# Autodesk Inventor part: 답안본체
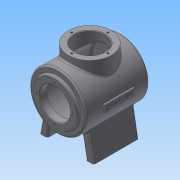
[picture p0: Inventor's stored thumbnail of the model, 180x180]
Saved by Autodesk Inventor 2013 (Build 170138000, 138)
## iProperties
Created: 2015-01
Part Number: 답안본체
Material: 일반
Document SubType Name: Modeling
Designer: Administrator
Density: 1 g/cm^3
Author: Administrator
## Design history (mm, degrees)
sketch "스케치1"
  geometry: C1 r 50 at (0, 0); C2 r 45 at (0, 0); 1 further point
  constraints: 2 centre point, 2 coincident
  dimensions: "d0" = 100 diameter of C1; "d1" = 90 diameter of C2
extrude "돌출1" new body sketch "스케치1" stored distance "d2" = 112; taper "d3" = 0 deg
extrude "돌출2" cut sketch "스케치1" distance "d4" = 48; taper "d5" = 0 deg; dims "d73" = 49, "d74" = 0
sketch "스케치2"
  geometry: C1 r 50 at (0, 0) reference; C2 r 38 at (0, 0)
  constraints: 1 centre point, 1 coincident
  dimensions: "d6" = 76 diameter of C2
extrude "돌출3" join sketch "스케치2" distance "d7" = 5; taper "d8" = 0 deg
hole "구멍1" diameter "d11" = 54; stored, may be unused: countersink angle "d15" = 90 deg, drill point angle "d17" = 118 deg; dims "d9" = 10, "d10" = 10, "d12" = 6, "d13" = 4, "d14" = 2, "d16" = 8
sketch "스케치3"
  geometry: C1 r 27 at (0, 0) reference; 1 further point
  constraints: 1 vertical alignment
  dimensions: "d18" = 32 distance of C1.centre point (0, 32)
hole "구멍2" sketch "스케치3" at (0, 32) diameter "d19" = 3.242; stored, may be unused: countersink angle "d23" = 90 deg, drill point angle "d25" = 118 deg; dims "d20" = 8, "d21" = 4, "d22" = 2, "d24" = 10
sketch "스케치4"
  geometry: L1 (-48, -80)-(-34, -80); L2 (-34, -80)-(-27.282, -41.901); L3 (-48, -80)-(-39.336, -30.865); C1 r 45 at (0, 0) reference; A1 r 50 centre (0, 0) between (-39.336, -30.865) and (-27.282, -41.901) reference; 1 further point
  constraints: 6 end point, 2 point on circle, 1 horizontal, 1 parallel
  dimensions: "d29" = 14 distance of L1.start L1.end; "d31" = 80 distance from line of L1 point (0, 0); "d32" = 48 horizontal distance of point (0, 0) L1.start; "d33" = 80 deg angle of L1 L2
extrude "돌출4" join sketch "스케치4" stored distance "d34" = 80; taper "d35" = 0 deg
node "작업 평면1"
sketch "스케치5"
  geometry: L1 (38, -61)-(-38, -61) reference; C1 r 38 at (0, -1); 1 further point
  constraints: 1 centre point, 1 vertical alignment
  dimensions: "d37" = 76 diameter of C1; "d38" = 60 distance from line of C1.centre L1
extrude "돌출5" join sketch "스케치5" stored distance "d39" = 80; taper "d40" = 0 deg
sketch "스케치6"
  geometry: L1 (-38, -62)-(38, -62) reference; C1 r 27 at (0, 0); C2 r 38 at (0, 0) reference; 1 further point
  constraints: 1 centre point, 1 coincident
  dimensions: "d41" = 54 diameter of C1
extrude "돌출6" cut sketch "스케치6" distance "d42" = 50; taper "d43" = 0 deg
sketch "스케치7"
  geometry: C1 r 38 at (0, 0) reference; C2 r 27 at (0, 0) reference; 1 further point
  constraints: 1 vertical alignment
  dimensions: "d71" = 32 distance of C2.centre point (0, 32)
hole "구멍3" sketch "스케치7" at (0, 32) diameter "d45" = 3.242; stored, may be unused: countersink angle "d49" = 90 deg, drill point angle "d51" = 118 deg; dims "d46" = 8, "d47" = 4, "d48" = 2, "d50" = 10
node "작업 평면3"
  node "작업 평면2"
sketch "스케치8"
  geometry: L1 (6, 26)-(-6, 26); L2 (-6, 26)-(-6, -28); L3 (-6, -28)-(6, -28); L4 (6, -28)-(6, 26); L5 (38, 61)-(-38, 61) reference; L6 (6, -1)-(20.992, -1); 2 further points
  constraints: 10 end point, 3 parallel, 2 midpoint, 1 horizontal, 1 perpendicular, 1 vertical alignment
  dimensions: "d56" = 12 distance of L3.end L2.end; "d57" = 54 distance of L2.end L1.end; "d59" = 62 distance between parallel lines of L6 L5
extrude "돌출7" join sketch "스케치8" stored distance "d60" = 50; taper "d61" = 0 deg
sketch "스케치9"
  geometry: L1 (-26, 6)-(-26, -6) reference; L2 (28, 6)-(-26, 6) reference; 4 further points
  constraints: 2 midpoint, 1 horizontal alignment, 1 vertical alignment, 1 other
feature "엠보싱1" sketch "스케치9" dims "d3" = 0, "d25" = 118 deg, "d62" = 0.5, "d63" = 0
chamfer "모따기1" distance "d64" = 1; stored, may be unused: second distance "d65" = 2, angle "d66" = 45 deg
fillet "모깎기1" dims "d67" = 3
fillet "모깎기2" dims "d68" = 3
fillet "모깎기3" dims "d69" = 3
fillet "모깎기4" dims "d70" = 3
node "솔리드1"
pattern_circular "원형 패턴1" dims angle "d27" = 360 deg
mirror "대칭1"
mirror "대칭2"
pattern_circular "원형 패턴2" dims angle "d53" = 360 deg
node "절단 모서리 투영1"
other parameters: "d36" = 62, "d55" = 2
